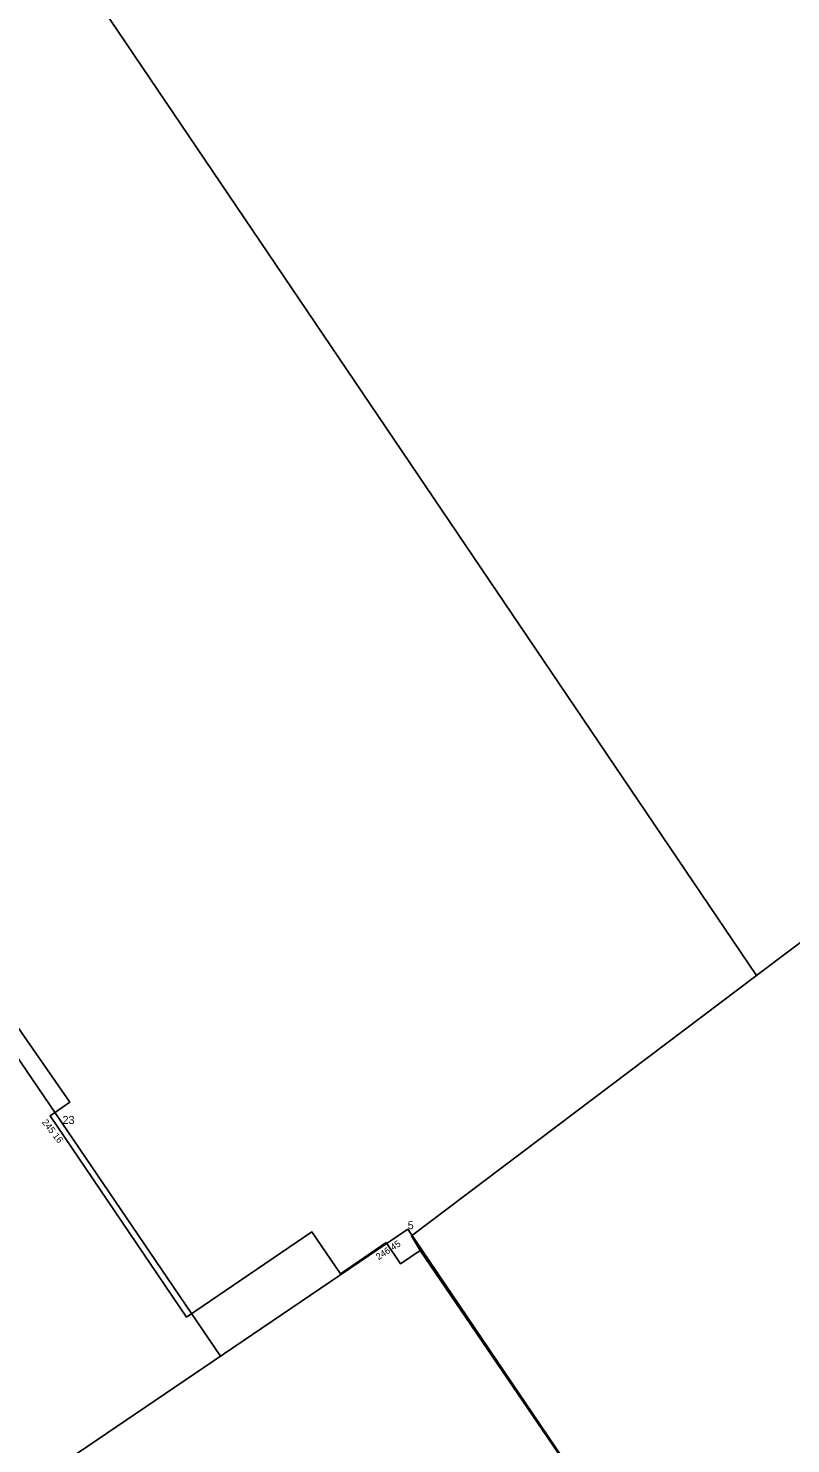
# Model space of a CAD drawing. Extents: x -675895 to -675697, y -1071173 to -1070976.
# Drawn here: x -675774.1 to -675745.5, y -1071102.1 to -1071049.1 of the extents above; entities that cross this region are included whole.
import ezdxf

# ---------------------------------------------------------------- set-up
doc = ezdxf.new("R2010")
doc.units = 0
for name, color, linetype in [('Vrstva 1', 7, 'Continuous'), ('Vrstva 2', 7, 'Continuous'), ('Vrstva 3', 7, 'Continuous'), ('Vrstva 4', 7, 'Continuous'), ('Vrstva 50', 7, 'Continuous')]:
    doc.layers.add(name, color=color, linetype=linetype)

msp = doc.modelspace()

# ---------------------------------------------------------------- linework, layer by layer
at = {"layer": 'Vrstva 1'}
for p, q in [((-675772.8, -1071090.16), (-675772.8, -1071090.16)), ((-675759.86, -1071094.11), (-675759.86, -1071094.11))]:
    msp.add_line(p, q, dxfattribs=at)
at = {"layer": 'Vrstva 4'}
for points in [[(-675812.98, -1071031.02), (-675806.86, -1071040.03), (-675803.05, -1071045.63), (-675783.85, -1071073.91), (-675766.881, -1071098.872)], [(-675759.86, -1071094.11), (-675774.41, -1071103.98), (-675790.18, -1071114.68), (-675803.94, -1071124.02), (-675804.68, -1071124.52)], [(-675759.86, -1071094.11), (-675754.04, -1071102.69), (-675748.4, -1071110.99)]]:
    msp.add_lwpolyline(points, dxfattribs=at)
at = {"layer": 'Vrstva 50'}
for p, q in [((-675746.78, -1071084.6), (-675725.92, -1071068.84)), ((-675748.85, -1071110.38), (-675759.39, -1071094.9))]:
    msp.add_line(p, q, dxfattribs=at)
for points in [[(-675833.97, -1070985.62), (-675832.35, -1070984.52), (-675810.01, -1070991.1), (-675746.78, -1071084.6)], [(-675759.39, -1071094.9), (-675760.13, -1071095.41), (-675760.67, -1071094.61), (-675762.38, -1071095.78), (-675763.45, -1071094.21), (-675768.15, -1071097.4), (-675773.27, -1071089.86), (-675772.53, -1071089.35), (-675775.52, -1071085.06), (-675776.21, -1071085.53), (-675790.24, -1071064.86), (-675789.62, -1071064.44), (-675792.36, -1071060.51), (-675792.93, -1071060.9), (-675794.05, -1071059.25)], [(-675759.39, -1071094.9), (-675759.72, -1071094.35), (-675746.78, -1071084.6)]]:
    msp.add_lwpolyline(points, dxfattribs=at)

# ---------------------------------------------------------------- texts
at = {"layer": 'Vrstva 2'}
for s, p in [('23', (-675772.8, -1071090.16)), ('5', (-675759.86, -1071094.11))]:
    msp.add_text(s, height=0.3, dxfattribs=at).set_placement(p)
at = {"layer": 'Vrstva 3'}
for s, rotation, p in [('245 16 ', 308.2661, (-675773.588, -1071090.106)), ('246 45 ', 33.4575, (-675760.951, -1071095.275))]:
    msp.add_text(s, height=0.25, rotation=rotation, dxfattribs=at).set_placement(p)

doc.saveas('drawing.dxf')
